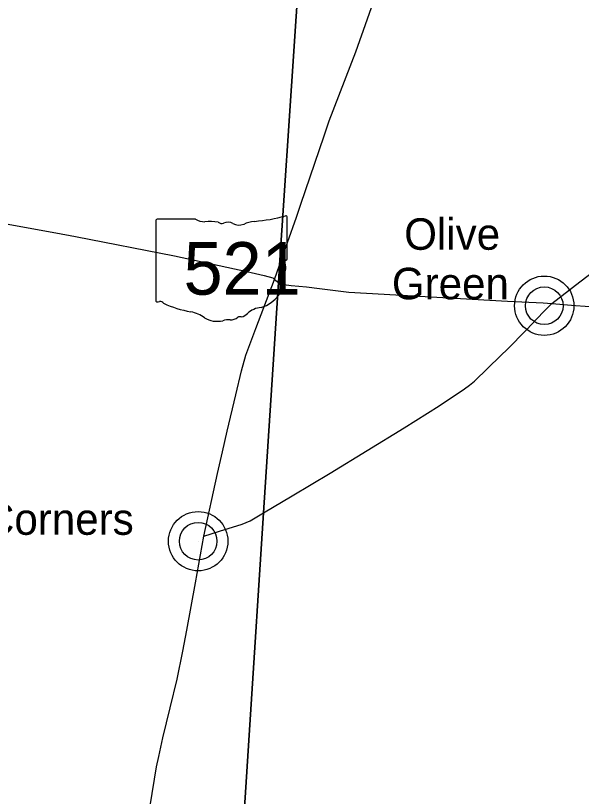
# Model space of a CAD drawing. Extents: x 1674899 to 2057726, y 653888 to 988278.
# Drawn here: x 1869393 to 1876887, y 838394 to 848737 of the extents above; entities that cross this region are included whole.
import ezdxf

# ---------------------------------------------------------------- set-up
doc = ezdxf.new("R2010")
doc.units = 0
for name, color, linetype in [('GM_X_County_Road', 7, 'Continuous'), ('GM_X_State_Location', 7, 'Continuous'), ('GM_X_State_Route', 7, 'Continuous'), ('GM_X_State_Shield', 7, 'Continuous'), ('GM_X_Township', 7, 'Continuous'), ('GM_X_Unincorporated', 7, 'Continuous'), ('GM_X_Unincorporated_Location', 7, 'Continuous'), ('GM_X_Unincorporated_Text', 7, 'Continuous')]:
    doc.layers.add(name, color=color, linetype=linetype)

msp = doc.modelspace()

# ---------------------------------------------------------------- linework, layer by layer
at = {"layer": 'GM_X_County_Road'}
msp.add_lwpolyline([(1876497, 844924), (1876809, 844899), (1877320, 844863)], dxfattribs=at)
at = {"layer": 'GM_X_State_Route'}
for points in [[(1871032, 837400), (1871261, 838785), (1871288, 838923), (1871345, 839169), (1871441, 839565), (1871531, 839946), (1871607, 840316), (1871659, 840595), (1871776, 841222), (1871888, 841839), (1872065, 842672), (1872135, 842960), (1872195, 843231), (1872309, 843713), (1872385, 844033), (1872444, 844239), (1872573, 844591), (1872823, 845242), (1872889, 845433), (1872993, 845731), (1873113, 846066), (1873172, 846240), (1873478, 847144), (1873548, 847343), (1873901, 848259), (1874595, 850236)], [(1869221, 845989), (1869925, 845860), (1870186, 845810), (1871499, 845553), (1872455, 845346), (1872684, 845295), (1872802, 845263), (1872823, 845242), (1872874, 845201), (1872899, 845188), (1872917, 845181), (1872945, 845174), (1873042, 845161), (1873246, 845142), (1873416, 845122), (1873807, 845072), (1875906, 844954), (1876379, 844930), (1876497, 844924)], [(1875906, 844320), (1876154, 844572), (1876386, 844812), (1876497, 844924), (1876868, 845210), (1877089, 845378), (1877250, 845505), (1877281, 845529), (1877348, 845583), (1877908, 846019)], [(1871888, 841839), (1872092, 841906), (1872394, 841999), (1872499, 842046), (1872678, 842151), (1873057, 842376), (1873560, 842674), (1874539, 843277), (1875001, 843568), (1875337, 843791), (1875406, 843841), (1875471, 843896), (1875822, 844235), (1875906, 844320)]]:
    msp.add_lwpolyline(points, dxfattribs=at)
at = {"layer": 'GM_X_State_Shield'}
for p, q in [((1871249, 846022), (1871249, 844965)), ((1871775, 846040), (1871266, 846040)), ((1872989, 845513), (1872989, 846066)), ((1872989, 845513), (1872989, 845513))]:
    msp.add_line(p, q, dxfattribs=at)
for centre, major_axis, start_param, end_param in [((1872369, 847480), (1845, 0), 4.814394, 5.042369), ((1872970, 846068), (19.4, 0), 6.141152, 7.989035), ((1871269, 846024), (20.2, 0), 1.712693, 3.28349), ((1871897, 846163), (196, 0), 4.042523, 4.731795), ((1871962, 845447), (702, 0), 1.404758, 1.657858), ((1872121, 846029), (56.4, 0), 3.836095, 5.185415), ((1872204, 845907), (117, 0), 0.950623, 2.079405), ((1872355, 846075), (141, 0), 4.081561, 5.145723), ((1872604, 845717), (371, 0), 1.699011, 2.107814), ((1872984, 845473), (30, 0), 1.883978, 3.671073), ((1872794, 845403), (180, 0), 5.934695, 6.695948), ((1872968, 845511), (20.7, 0), 5.05454, 6.418171), ((1873058, 845282), (131, 0), 2.387724, 3.262537), ((1872472, 845212), (462, 0), 5.101752, 6.440018), ((1871269, 844963), (20.3, 0), 3.00124, 4.508301), ((1871272, 845071), (155, 0), 4.665946, 4.897461), ((1871304, 844904), (56, 0), 0.519207, 1.627899), ((1872010, 845853), (1333, 0), 4.195997, 4.488961), ((1872667, 844668), (253, 0), 1.647645, 2.488434), ((1871613, 844490), (417, 0), 0.823519, 1.323587), ((1872064, 844899), (265, 0), 4.026481, 4.996735), ((1872236, 844820), (141, 0), 4.691044, 5.507374), ((1872364, 844717), (39.7, 0), 1.147584, 2.315152), ((1872347, 844863), (149, 0), 4.937069, 5.64225), ((1872217, 844534), (217, 0), 1.495662, 1.94098)]:
    msp.add_ellipse(centre, major_axis=major_axis, ratio=0.8, start_param=start_param, end_param=end_param, dxfattribs=at)
at = {"layer": 'GM_X_Township'}
for points in [[(1850615, 859080), (1861827, 858324), (1863977, 858188), (1869100, 857855), (1873671, 857558), (1873447, 853777), (1873266, 851105), (1872889, 845433), (1872874, 845201), (1872678, 842151), (1872497, 839344), (1872306, 836385), (1871965, 831096), (1871301, 831135), (1870943, 831158), (1868637, 831266), (1861106, 831707), (1859467, 831803), (1858606, 831851), (1854821, 832136)], [(1872306, 836385), (1872497, 839344), (1872678, 842151), (1872874, 845201), (1872889, 845433), (1873266, 851105), (1873447, 853777), (1873671, 857558), (1876143, 857428), (1879641, 857188), (1882352, 856998), (1886895, 856734), (1890695, 856480), (1891588, 856432), (1891937, 856405), (1896895, 856116), (1900228, 855908), (1900008, 852727), (1899571, 846055), (1899210, 840637), (1899208, 840537), (1899202, 840435), (1898887, 835373)]]:
    msp.add_lwpolyline(points, dxfattribs=at)
at = {"layer": 'GM_X_Unincorporated'}
for centre, radius in [((1876395, 844894), 393), ((1876395, 844894), 249), ((1871811, 841774), 393), ((1871811, 841774), 249)]:
    msp.add_circle(centre, radius, dxfattribs=at)
at = {"layer": 'GM_X_Unincorporated_Location'}
for p, q in [((1876395, 844894), (1876395, 844894)), ((1871811, 841774), (1871811, 841774))]:
    msp.add_line(p, q, dxfattribs=at)

# ---------------------------------------------------------------- texts
at = {"layer": 'GM_X_State_Location'}
msp.add_text('521', height=1, rotation=0, dxfattribs=at).set_placement((1871746, 845350))
for s in ['s', 'r']:
    msp.add_text(s, height=1, dxfattribs=at).set_placement((1872099, 845423))
at = {"layer": 'GM_X_State_Shield'}
msp.add_text('521', height=696.1, dxfattribs=at).set_placement((1871617, 845040))
at = {"layer": 'GM_X_Unincorporated_Text'}
for s, p in [('Olive', (1874540, 845635)), ('Green', (1874377, 844979)), ('Stark Corners', (1867518, 841859))]:
    msp.add_text(s, height=417, rotation=0, dxfattribs=at).set_placement(p)

doc.saveas('drawing.dxf')
